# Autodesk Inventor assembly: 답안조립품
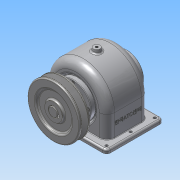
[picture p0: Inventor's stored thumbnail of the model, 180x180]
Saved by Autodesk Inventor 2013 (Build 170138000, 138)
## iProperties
Created: 2015-09
Part Number: 답안조립품
Document SubType Name: Assembly
Designer: Administrator
Author: Administrator
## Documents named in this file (14)
- C:\Users\Administrator\Desktop\450908V1030\답안조립품.iam
- C:\Users\Administrator\Desktop\450908V1030\본체.ipt
- C:\Users\Administrator\Desktop\450908V1030\베어링 6203.ipt
- C:\Users\Administrator\Desktop\450908V1030\뒤커버.ipt
- C:\Users\Administrator\Desktop\450908V1030\볼트 M3 x 8.ipt
- C:\Users\Administrator\Desktop\450908V1030\앞커버.ipt
- C:\Users\Administrator\Desktop\450908V1030\볼트 M3 x 10.ipt
- C:\Users\Administrator\Desktop\450908V1030\축.ipt
- C:\Users\Administrator\Desktop\450908V1030\키 - 6 x 6 x 22.ipt
- C:\Users\Administrator\Desktop\450908V1030\스퍼기어.ipt
- C:\Users\Administrator\Desktop\450908V1030\오일 실 17 32 8.ipt
- C:\Users\Administrator\Desktop\450908V1030\V-벨트풀리.ipt
- C:\Users\Administrator\Desktop\450908V1030\키 - 5 x 5 x 18.ipt
- C:\Users\Administrator\Desktop\450908V1030\멈춤나사 - M4x10.ipt
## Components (9 placed, 3 different names)
1. V-벨트풀리:1 — 각도:4
2. ISO 4762 M3 x 8:1
3. ISO 4762 M3 x 8:2
4. ISO 4762 M3 x 8:3
5. ISO 4762 M3 x 8:4
6. ISO 4762 M3 x 10:1
7. ISO 4762 M3 x 10:2
8. ISO 4762 M3 x 10:3
9. ISO 4762 M3 x 10:4
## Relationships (1: Angle 1)
- 각도:4 [Angle]: V-벨트풀리:1
